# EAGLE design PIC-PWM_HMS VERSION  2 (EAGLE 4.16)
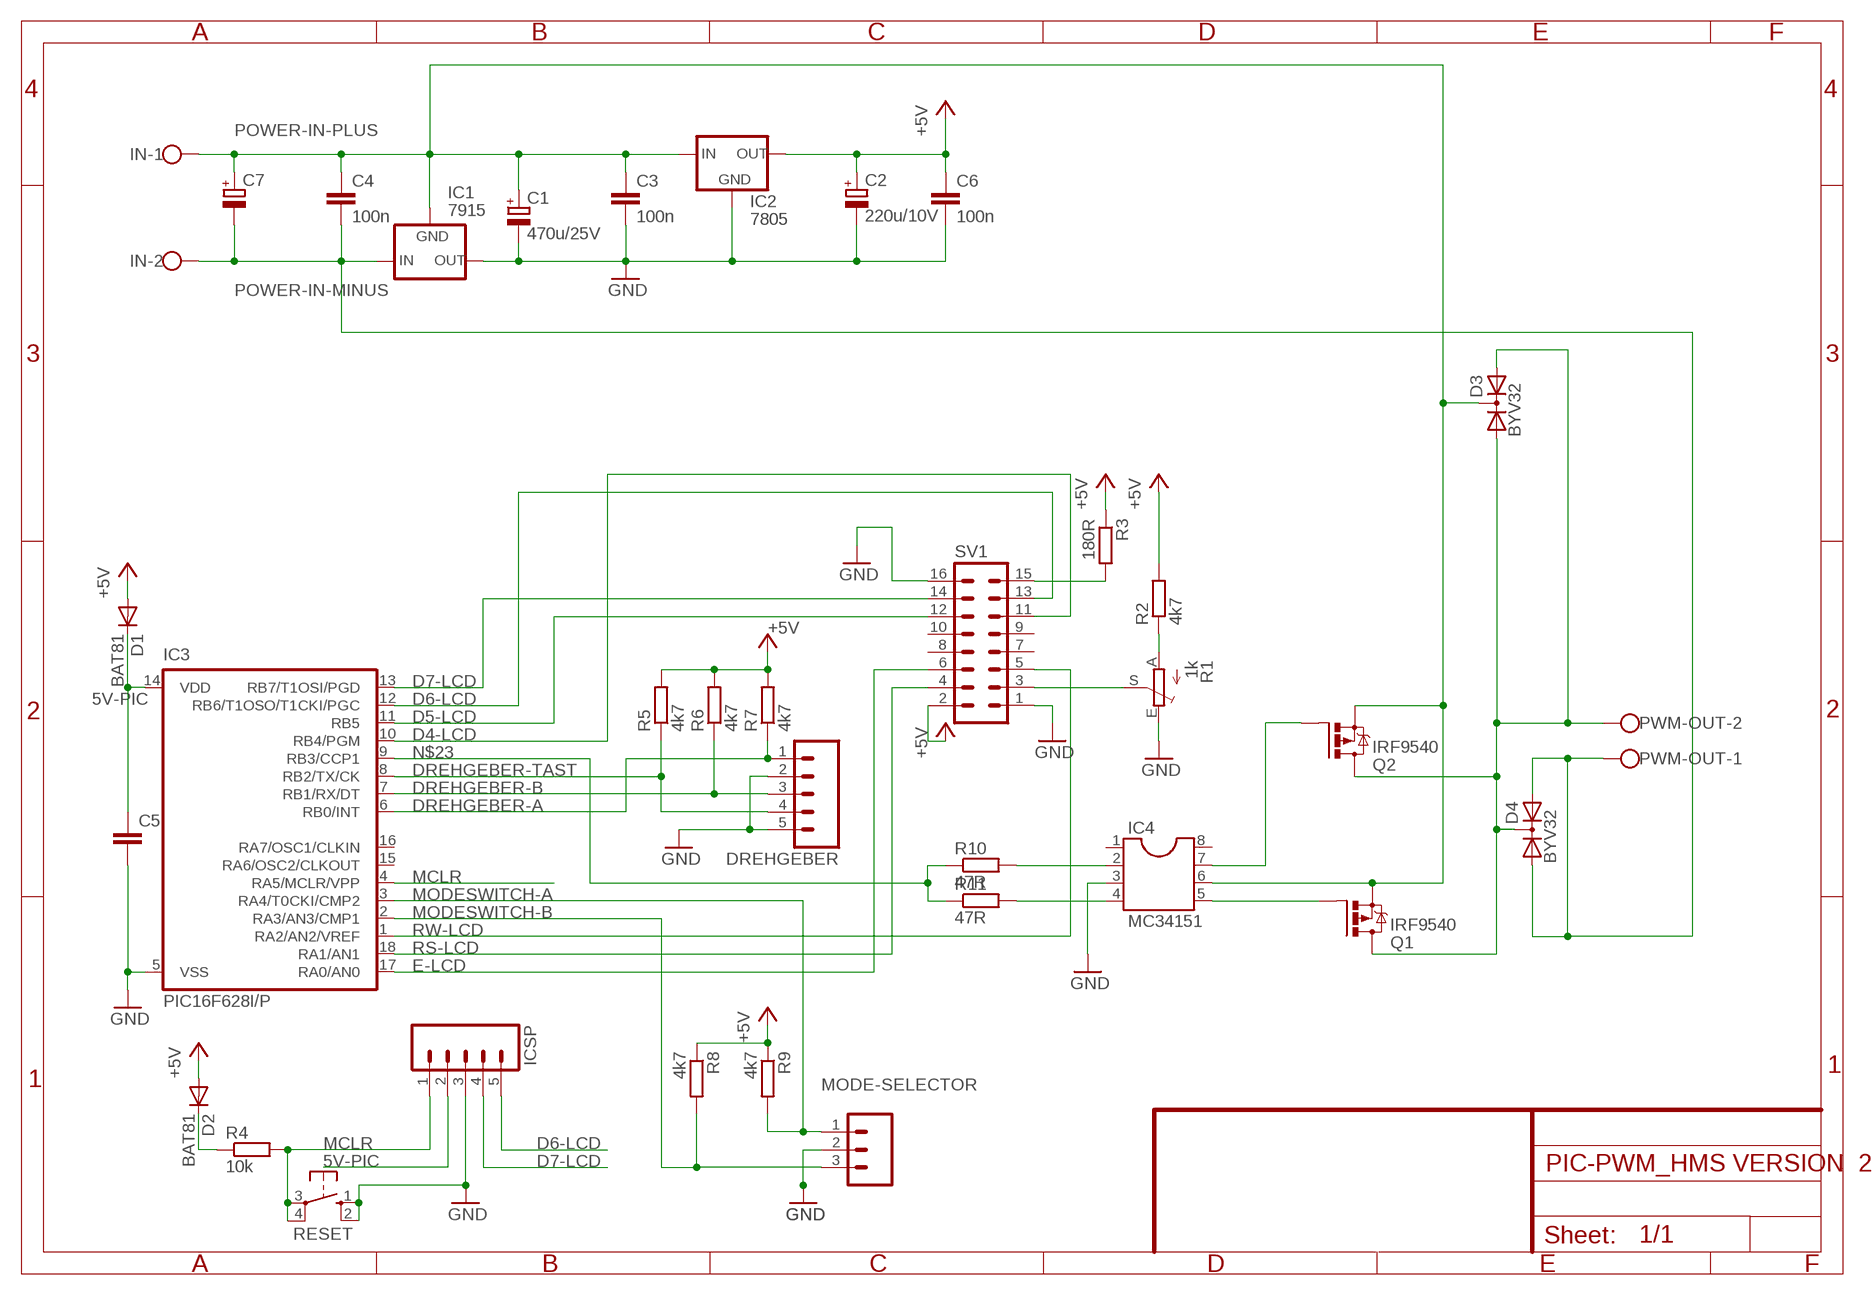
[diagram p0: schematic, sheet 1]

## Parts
C1  470u/25V  CPOL-EUE5-13  [E5-13]
C2  220u/10V  CPOL-EUE5-8.5  [E5-8,5]
C3  100n  C-EU050-024X044  [C050-024X044]
C4  100n  C-EU050-024X044  [C050-024X044]
C5  C-EU050-024X044  [C050-024X044]
C6  100n  C-EU050-024X044  [C050-024X044]
C7  CPOL-EUE10-25  [EB25D]
D1  BAT81  [DO34-7]
D2  BAT81  [DO34-7]
D3  BYV32  [TO220ABS]
D4  BYV32  [TO220ABS]
DREHGEBER  M05  [05P]
IC1  7915  79XXS  [79XXS]
IC2  7805  78MXXS  [78MXXS]
IC3  PIC16F628I/P  [DIL18]
IC4  MC34151  DIL8  [DIL08]
ICSP  M05  [05P]
IN  W237-02P  [W237-132]
MODE-SELECTOR  M03  [03P]
PWM-OUT  W237-02P  [W237-132]
Q1  IRF9540  [TO220BV]
Q2  IRF9540  [TO220BV]
R1  1k  TRIM_EU-CA9V  [CA9V]
R2  4k7  R-EU_0207/12  [0207/12]
R3  180R  R-EU_0309/12  [0309/12]
R4  10k  R-EU_0207/12  [0207/12]
R5  4k7  R-EU_0207/12  [0207/12]
R6  4k7  R-EU_0207/12  [0207/12]
R7  4k7  R-EU_0207/12  [0207/12]
R8  4k7  R-EU_0207/12  [0207/12]
R9  4k7  R-EU_0207/12  [0207/12]
R10  47R  R-EU_0207/12  [0207/12]
R11  47R  R-EU_0207/12  [0207/12]
RESET  10-XX  [B3F-10XX]
SV1  ML16  [ML16]

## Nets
5V-PIC: C5.1 D1.C IC3.14(VDD) ICSP.2
+5V: C2.+ C6.1 D1.A D2.A IC2.OUT R2.2 R3.1 R5.2 R6.2 R7.2 R8.1 R9.1 SV1.2
D4-LCD: IC3.10(RB4/PGM) SV1.11
D5-LCD: IC3.11(RB5) SV1.12
D6-LCD: IC3.12(RB6/T1OSO/T1CKI/PGC) ICSP.5 SV1.13
D7-LCD: IC3.13(RB7/T1OSI/PGD) ICSP.4 SV1.14
DREHGEBER-A: DREHGEBER.1 IC3.6(RB0/INT) R7.1
DREHGEBER-B: DREHGEBER.3 IC3.7(RB1/RX/DT) R6.1
DREHGEBER-TAST: DREHGEBER.4 IC3.8(RB2/TX/CK) R5.1
E-LCD: IC3.17(RA0/AN0) SV1.6
GND: C1.- C2.- C3.2 C5.2 C6.2 DREHGEBER.2 DREHGEBER.5 IC1.OUT IC2.GND IC3.5(VSS) IC4.3 ICSP.3 MODE-SELECTOR.2 R1.E RESET.1(S) RESET.2(S1) SV1.1 SV1.16
MCLR: IC3.4(RA5/MCLR/VPP) ICSP.1 R4.2 RESET.3(P) RESET.4(P1)
MODESWITCH-A: IC3.3(RA4/T0CKI/CMP2) MODE-SELECTOR.1 R9.2
MODESWITCH-B: IC3.2(RA3/AN3/CMP1) MODE-SELECTOR.3 R8.2
N$1: IC4.2 R10.2
N$2: IC4.4 R11.2
N$3: D2.C R4.1
N$4: R1.A R2.1
N$5: R1.S SV1.3
N$6: D3.A1 D3.A2 D4.C PWM-OUT.2 Q1.D Q2.D
N$8: IC4.5 Q1.G
N$9: IC4.7 Q2.G
N$11: R3.2 SV1.15
N$23: IC3.9(RB3/CCP1) R10.1 R11.1
POWER-IN-MINUS: C4.2 C7.- D4.A1 D4.A2 IC1.IN IN.2 PWM-OUT.1
POWER-IN-PLUS: C1.+ C3.1 C4.1 C7.+ D3.C IC1.GND IC2.IN IC4.6 IN.1 Q1.S Q2.S
RS-LCD: IC3.18(RA1/AN1) SV1.4
RW-LCD: IC3.1(RA2/AN2/VREF) SV1.5
Unconnected: IC3.15(RA6/OSC2/CLKOUT) IC3.16(RA7/OSC1/CLKIN) IC4.1 IC4.8 SV1.7 SV1.8 SV1.9 SV1.10

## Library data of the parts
C1 C2 C7 = rcl:CPOL-EU: POLARIZED CAPACITOR, European symbol
C3-C6 = rcl:C-EU: CAPACITOR, European symbol
D1 D2 = diode:BAT81: DIODE
D3 D4 = diode:BYV32: DIODE 2 x Si diode 200 V, 20 A/230 Apeak, 25 ns
DREHGEBER ICSP = con-amp-quick:M05: AMP QUICK CONNECTOR
IC1 = v-reg:79XXS: VOLTAGE REGULATOR
IC2 = v-reg:78MXXS: VOLTAGE REGULATOR
IC3 = microchip-5:PIC16F628*: MICROCONTROLLER PIC16F628(A) 16 I/O One 16-bit timer Two 8-bit timer Two comparators USART CCP/PWM Precision 4 MHz internal oscillator 2k Program Flash memory 224 bytes SRAM 128 bytes EEPROM
IC4 = ic-package:DIL8: Dual In Line
IN PWM-OUT = con-wago-508:W237-02P: WAGO SREW CLAMP
MODE-SELECTOR = con-amp-quick:M03: AMP QUICK CONNECTOR
Q1 Q2 = transistor-power:IRF9540: P-CHANNEL HEXFET POWER-MOS-FET Source: http://www.irf.com/product-info/datasheets/data/irf9530.pdf
R1 = pot:TRIM_EU-: POTENTIOMETER
R2-R11 = rcl:R-EU_: RESISTOR, European symbol
RESET = switch-omron:10-XX: OMRON SWITCH
SV1 = con-harting-ml:ML16: HARTING

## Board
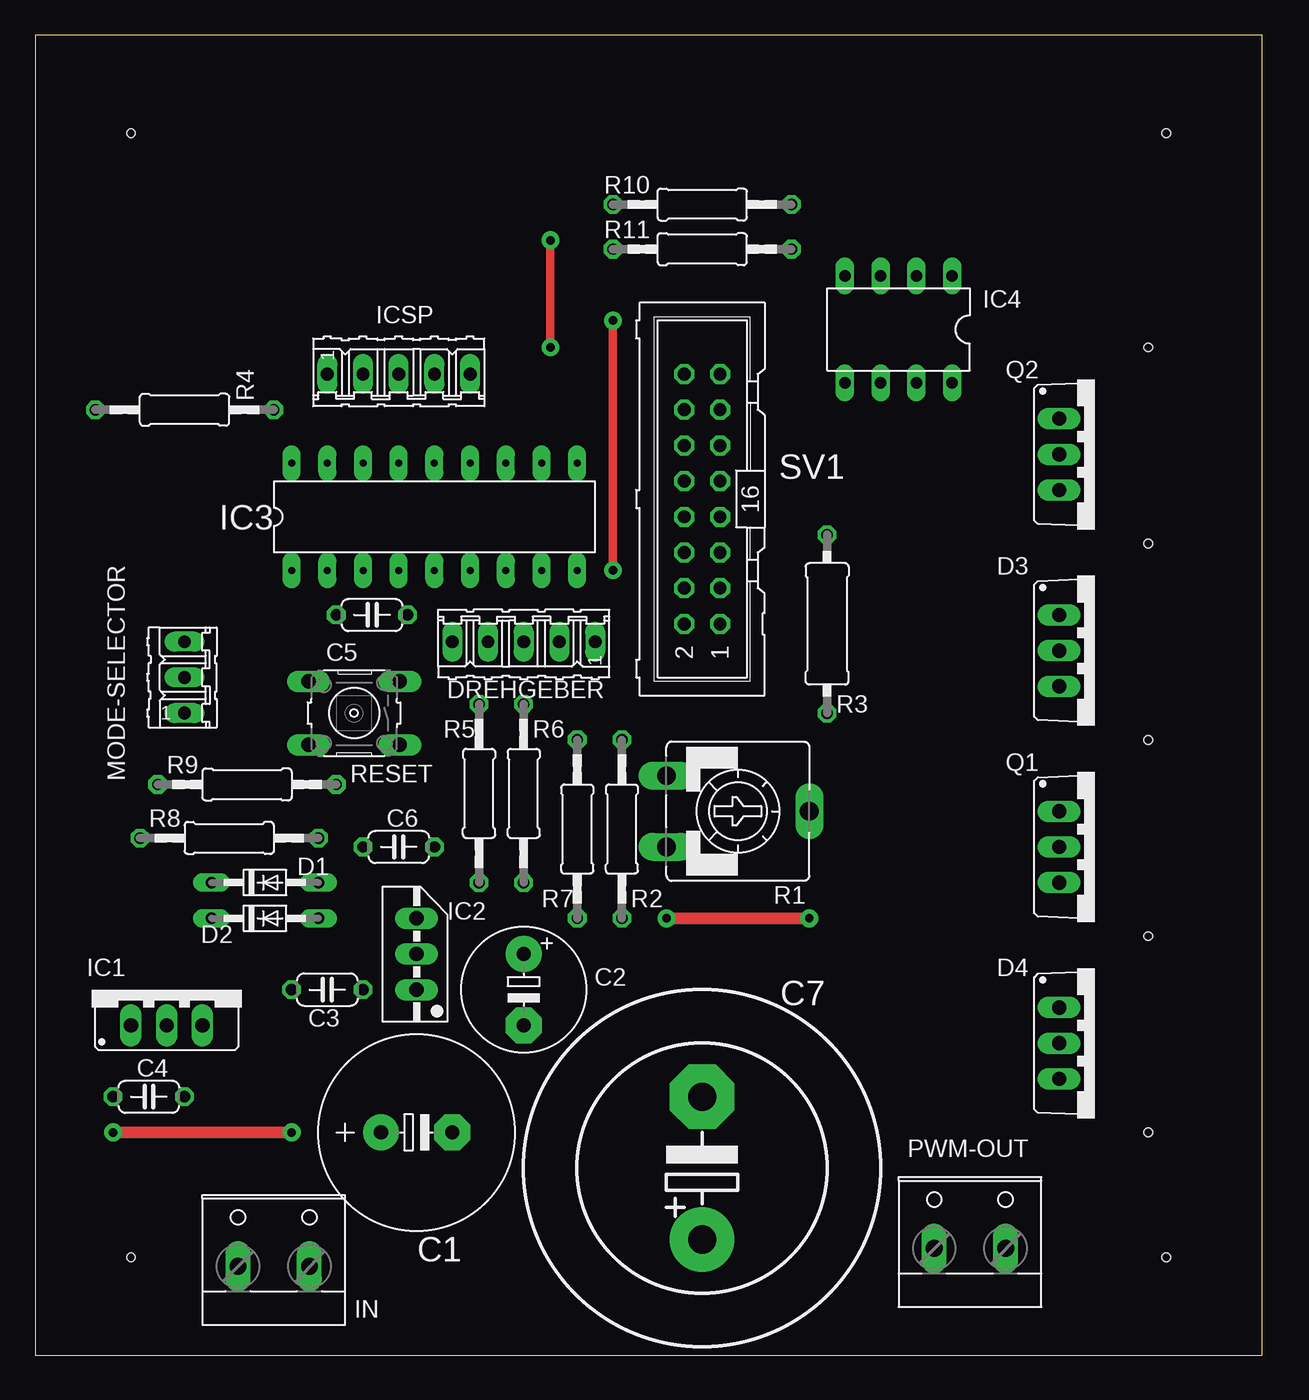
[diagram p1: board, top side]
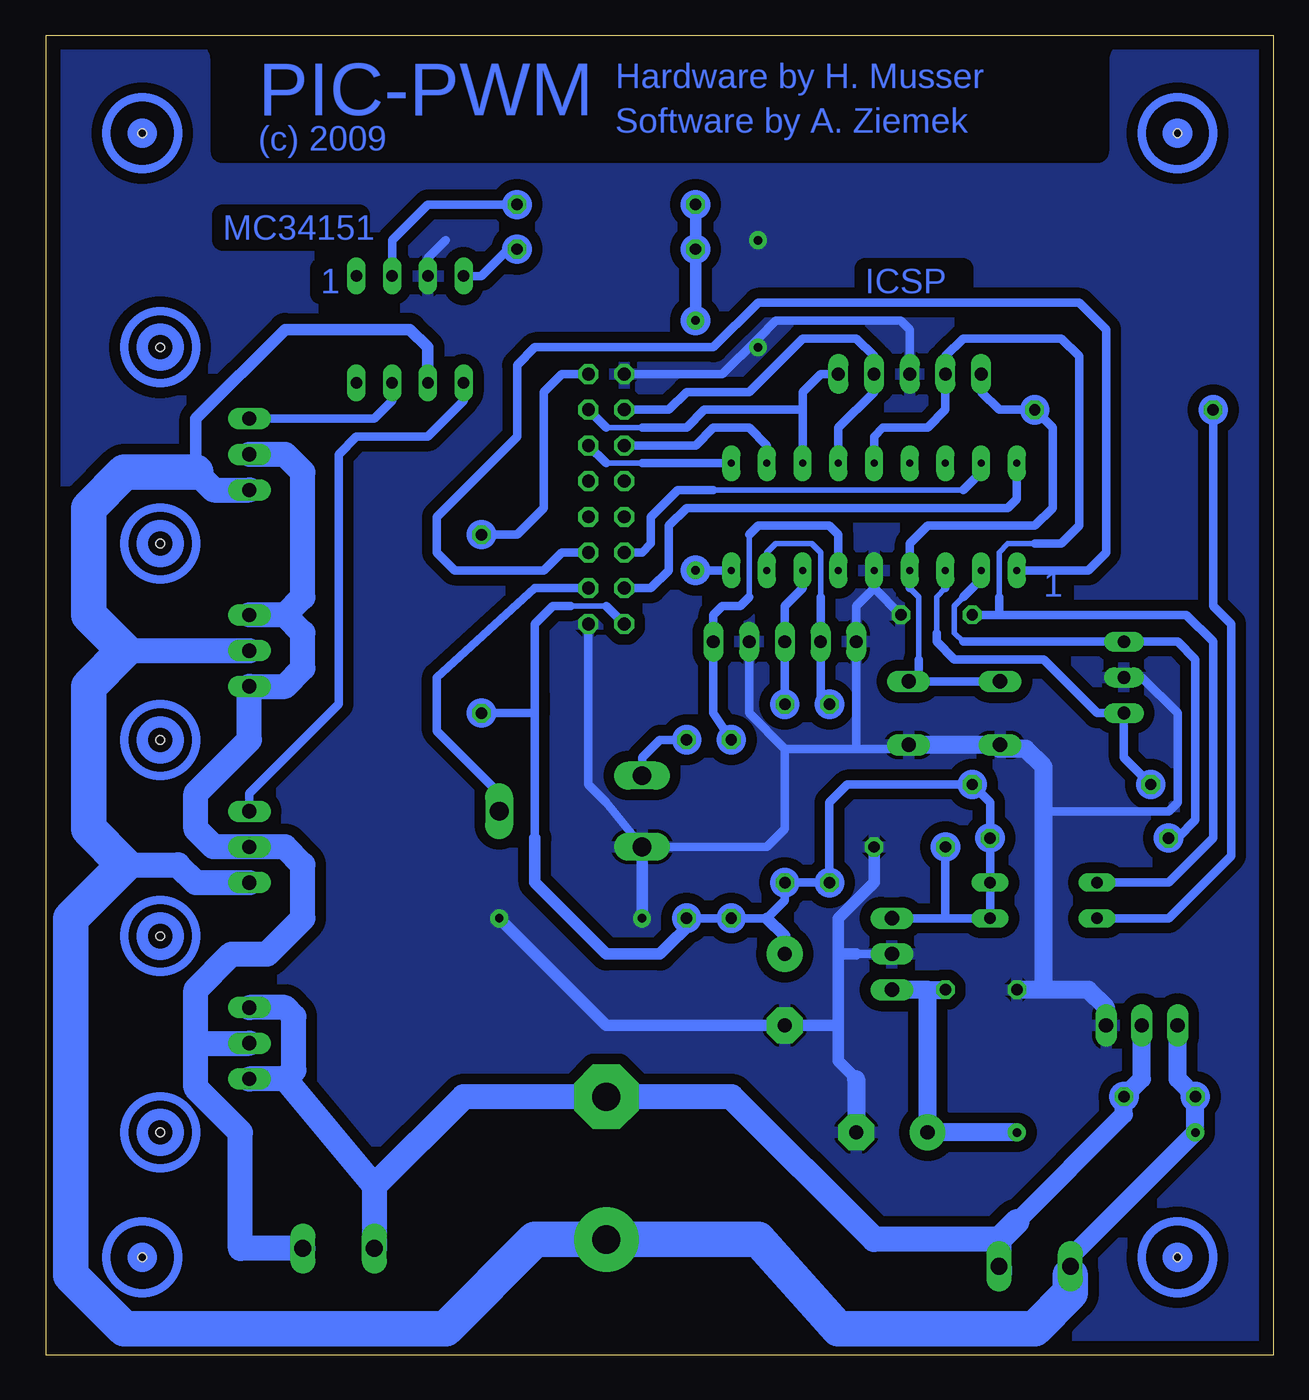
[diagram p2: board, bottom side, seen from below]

Size 87.3 x 93.96 mm. Coordinates in mm from the lower left corner, seen from the top.
Outline: 0,93.96 0,0 87.3,0 87.3,93.96 0,93.96
Copper layers (1*16): Top 0.035mm / dielectric 1.5mm / Bottom 0.035mm
Design rules "default": minimum track width 10mil, minimum drill 24mil, track to track 30mil, track to pad 30mil, pad to pad 30mil, via to via 30mil, smd to smd 30mil, copper to edge 40mil, drill to drill 8mil, minimum pad ring 10mil, minimum via ring 8mil, stop-mask expansion 4mil, vias tented up to drill 0mil, thermal gap 10mil
Holes 0.6 mm at 6.82,86.98 80.48,86.98 79.21,71.74 79.21,57.77 79.21,43.8 79.21,29.83 80.48,6.97 6.82,6.97 79.21,15.86

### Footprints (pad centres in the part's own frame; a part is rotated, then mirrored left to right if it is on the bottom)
E5-13 = drill 1.016 pad 2.54 round: + -2.54,0 | drill 1.016 pad 2.54 octagon: - 2.54,0
E5-8,5 = drill 1.016 pad 2.54 round: + -2.54,0 | drill 1.016 pad 2.54 octagon: - 2.54,0
C050-024X044 = drill 0.813 octagon: 1 -2.54,0; 2 2.54,0
EB25D = drill 2.007 pad 4.597 round: + -5.08,0 | drill 2.007 pad 4.597 octagon: - 5.08,0
DO34-7 = drill 0.813 long: A 3.81,0; C -3.81,0
TO220ABS = drill 1.016 long: A1 -2.54,-2.54; A2 2.54,-2.54; C 0,-2.54
05P = drill 0.914 long: 1 -5.08,0; 2 -2.54,0; 3 0,0; 4 2.54,0; 5 5.08,0
79XXS = drill 1.016 long: GND -2.54,-2.54; IN 0,-2.54; OUT 2.54,-2.54
78MXXS = drill 1.016 long: GND 0,-2.54; IN -2.54,-2.54; OUT 2.54,-2.54
DIL18 = drill 0.5 pad 1.27 long: 1 -10.16,-3.81; 2 -7.62,-3.81; 3 -5.08,-3.81; 4 -2.54,-3.81; 5 0,-3.81; 6 2.54,-3.81; 7 5.08,-3.81; 8 7.62,-3.81; 9 10.16,-3.81; 10 10.16,3.81; 11 7.62,3.81; 12 5.08,3.81; 13 2.54,3.81; 14 0,3.81; 15 -2.54,3.81; 16 -5.08,3.81; 17 -7.62,3.81; 18 -10.16,3.81
DIL08 = drill 0.813 long: 1 -3.81,-3.81; 2 -1.27,-3.81; 3 1.27,-3.81; 4 3.81,-3.81; 5 3.81,3.81; 6 1.27,3.81; 7 -1.27,3.81; 8 -3.81,3.81
W237-132 = drill 1.194 long: 1 -2.54,-0.635; 2 2.54,-0.635
03P = drill 0.914 long: 1 -2.54,0; 2 0,0; 3 2.54,0
TO220BV = drill 1.016 long: D 0,-2.54; G -2.54,-2.54; S 2.54,-2.54
CA9V = drill 1.321 long: A -2.54,-5.08; E 2.54,-5.08; S 0,5.08
0207/12 = drill 0.813 octagon: 1 -6.35,0; 2 6.35,0
0309/12 = drill 0.813 octagon: 1 -6.35,0; 2 6.35,0
B3F-10XX = drill 1.016 long: 1 -3.251,2.261; 2 3.251,2.261; 3 -3.251,-2.261; 4 3.251,-2.261
ML16 = drill 0.914 octagon: 1 -8.89,-1.27; 2 -8.89,1.27; 3 -6.35,-1.27; 4 -6.35,1.27; 5 -3.81,-1.27; 6 -3.81,1.27; 7 -1.27,-1.27; 8 -1.27,1.27; 9 1.27,-1.27; 10 1.27,1.27; 11 3.81,-1.27; 12 3.81,1.27; 13 6.35,-1.27; 14 6.35,1.27; 15 8.89,-1.27; 16 8.89,1.27

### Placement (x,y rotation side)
C1  27.14,15.86 0 top
C2  34.76,26.02 270 top
C3  20.79,26.02 180 top
C4  8.09,18.4 0 top
C5  23.96,52.69 0 top
C6  25.87,36.18 0 top
C7  47.46,13.32 90 top
D1  16.34,33.64 0 top
D2  16.34,31.1 0 top
D3  75.4,50.15 270 top
D4  75.4,22.21 270 top
DREHGEBER  34.76,50.79 180 top
IC1  9.36,26.02 0 top
IC2  24.6,28.56 90 top
IC3  28.41,59.68 0 top
IC4  61.43,73.01 180 top
ICSP  25.87,69.83 0 top
IN  16.98,6.97 0 top
MODE-SELECTOR  10.63,48.25 90 top
PWM-OUT  66.51,8.24 0 top
Q1  75.4,36.18 270 top
Q2  75.4,64.12 270 top
R1  50,38.72 270 top
R2  41.75,37.45 270 top
R3  56.35,52.05 90 top
R4  10.63,67.29 0 top
R5  31.58,39.99 270 top
R6  34.76,39.99 270 top
R7  38.57,37.45 270 top
R8  13.8,36.82 180 top
R9  15.07,40.62 180 top
R10  47.46,81.9 0 top
R11  47.46,78.72 0 top
RESET  22.7,45.7 180 top
SV1  47.46,60.95 90 top

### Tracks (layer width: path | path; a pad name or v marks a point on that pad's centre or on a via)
5V-PIC
  Bottom 0.406: 19.52,53.96 19.52,57.13 18.88,57.77 16.98,57.77
  Bottom 0.61: D1.C 7.46,33.64 4.28,36.82 4.28,50.79 6.19,52.69 19.52,52.69 | IC3.14 28.41,65.39 27.77,66.02 24.6,66.02 23.33,67.29 ICSP.2 23.33,71.1 22.06,72.38 15.07,72.38 13.8,71.1 13.8,59.04 15.07,57.77 16.98,57.77 | 19.52,52.69 C5.1 | 19.52,52.69 19.52,53.96
+5V
  Bottom 0.406: 50,53.33 47.46,53.33
  Bottom 0.61: 47.46,53.33 SV1.2 | 50,53.33 51.27,53.33 52.54,52.05 52.54,46.98 | 52.54,36.82 52.54,46.98 | R2.2 41.11,31.1 R7.2 36.03,31.1 34.76,32.37 R6.2 R5.2 31.58,39.36 30.31,40.62 R9.1 20.15,39.36 R8.1 D1.A D2.A 23.33,31.1 | 52.54,46.98 52.54,45.7 R3.1 | 23.33,31.1 IC2.OUT | 23.33,31.1 C6.1
  Bottom 0.813: C2.+ 34.76,29.83 36.03,31.1 | 52.54,36.82 52.54,33.64 47.46,28.56 43.65,28.56 41.11,31.1
D4-LCD
  Bottom 0.406: 44.92,63.49 47.46,63.49
  Bottom 0.61: 47.46,63.49 SV1.11 | IC3.10 44.92,63.49
D5-LCD
  Bottom 0.61: IC3.11 36.03,64.75 37.3,66.02 39.84,66.02 41.11,64.75 SV1.12
D6-LCD
  Bottom 0.406: 44.92,66.02 47.46,66.02
  Bottom 0.61: 47.46,66.02 SV1.13 | 44.92,66.02 41.75,66.02 40.48,67.29 33.49,67.29 | IC3.12 33.49,67.29 | 33.49,67.29 33.49,68.56 32.22,69.83 ICSP.5
D7-LCD
  Bottom 0.61: SV1.14 43.02,67.29 41.75,68.56 37.3,68.56 33.49,72.38 29.68,72.38 28.41,71.1 ICSP.4 28.41,68.56 30.95,66.02 IC3.13
DREHGEBER-A
  Bottom 0.406: 37.3,53.96 37.3,58.41
  Bottom 0.61: R7.1 39.84,45.7 DREHGEBER.1 39.84,52.69 39.21,53.33 37.94,53.33 37.3,53.96 | IC3.6 30.95,58.41 31.58,59.04 36.67,59.04 37.3,58.41
DREHGEBER-B
  Bottom 0.61: R6.1 DREHGEBER.3 34.76,53.33 33.49,54.59 IC3.7
DREHGEBER-TAST
  Bottom 0.406: 32.22,53.96 32.22,57.13 32.86,57.77 35.4,57.77 36.03,57.13 IC3.8
  Bottom 0.61: R5.1 32.22,46.98 DREHGEBER.4 32.22,53.96
E-LCD
  Bottom 0.406: 22.06,61.58 39.84,61.58
  Bottom 0.61: IC3.17 20.79,62.85 22.06,61.58 | 39.84,61.58 42.38,61.58 44.29,59.68 44.29,57.77 44.92,57.13 SV1.6
GND  (via drill 0.6 pad 1.27)
  Top 0.61: v36.67,71.74 v36.67,79.36
  Top 0.813: v44.92,31.1 v55.08,31.1
  Bottom 0.61: 28.41,54.59 IC3.5 | 28.41,54.59 29.68,53.33 DREHGEBER.5 29.68,43.16 | DREHGEBER.2 37.3,45.7 34.76,43.16 | 29.68,43.16 34.76,43.16 | SV1.1 48.73,40.62 47.46,39.36 R1.E 36.03,36.18 34.76,37.45 34.76,43.16 | 29.68,43.16 26.5,43.16 26.5,43.8 25.87,43.37 RESET.1 | MODE-SELECTOR.2 9.36,48.25 6.82,45.7 6.82,39.36 7.46,38.72 16.34,38.72 | 36.67,72.38 35.4,73.64 26.5,73.64 25.87,73.01 ICSP.3 | 36.67,72.38 39.21,69.83 SV1.16 | 28.41,54.59 C5.2 | 36.67,72.38 v36.67,71.74 | 58.89,79.36 60.16,78.09 IC4.3 | 30.95,28.56 30.95,31.1 | 29.68,28.56 IC2.GND
  Bottom 0.813: 29.68,28.56 30.95,28.56 30.95,23.48 | 30.95,23.48 C2.- | 29.68,19.67 30.95,20.94 30.95,23.48 | C6.2 28.41,33.64 30.95,31.1 30.95,23.48 | 30.95,23.48 47.46,23.48 v55.08,31.1 | R1.E v44.92,31.1
  Bottom 1.27: RESET.1 RESET.2 19.8,43.44 19.52,43.16 17.61,43.16 16.34,41.9 16.34,38.72 16.34,26.02 | 16.34,26.02 C3.2 | IC1.OUT 11.9,24.75 13.17,26.02 16.34,26.02 | 29.68,19.67 C1.-
  pour Bottom: 1.1,0.62 1.1,93.33 9.99,93.33 arc-90 11.26,92.06 11.26,85.71 arc90 12.54,84.44 74.77,84.44 arc90 76.03,85.71 76.03,92.06 arc-90 77.31,93.33 86.2,93.33 86.2,0.62
MCLR
  Bottom 0.406: 25.87,54.59 25.23,53.96 25.23,49.52
  Bottom 0.61: 26.5,48.25 25.87,48.25 | 26.5,48.25 26.58,48.17 RESET.3 | RESET.4 25.23,47.97 | 25.23,47.97 26.23,47.97 26.5,48.25 | ICSP.1 20.79,68.56 19.52,67.29 R4.2 15.71,66.02 15.71,60.31 16.98,59.04 24.6,59.04 25.87,57.77 IC3.4 25.87,54.59 | 25.23,47.97 25.23,49.52
MODESWITCH-A
  Bottom 0.406: 23.33,54.59 23.96,53.96 23.96,51.42
  Bottom 0.61: R9.2 10.63,42.53 MODE-SELECTOR.1 12.54,45.7 16.34,49.52 22.7,49.52 23.96,50.79 23.96,51.42 | 23.33,54.59 IC3.3
MODESWITCH-B
  Bottom 0.406: 22.06,53.96 22.7,53.33 22.7,51.42 22.06,50.79
  Bottom 0.61: R8.2 6.82,36.82 5.55,38.09 5.55,49.52 6.82,50.79 MODE-SELECTOR.3 22.06,50.79 | IC3.2 20.79,55.23 22.06,53.96
N$1
  Bottom 0.61: R10.2 60.16,81.9 62.7,79.36 IC4.2
N$2
  Bottom 0.61: R11.2 54.45,78.72 56.35,76.82 IC4.4
N$3
  Bottom 0.61: R4.1 4.28,53.33 3.01,52.05 3.01,35.55 7.46,31.1 D2.C
N$4
  Bottom 0.61: R2.1 43.65,43.8 44.92,42.53 R1.A
N$5
  Bottom 0.61: SV1.3 52.54,54.59 59.53,48.25 59.53,44.44 55.08,39.99 R1.S
N$6
  Bottom 1.778: PWM-OUT.2 73.5,7.61 73.5,15.86 76.67,19.04 76.67,22.21 | 76.67,22.21 D4.C | 76.67,22.21 76.67,26.02 74.13,28.56 71.59,28.56 69.05,31.1 69.05,34.91 70.32,36.18 Q1.D 75.4,36.18 76.67,37.45 76.67,39.99 72.86,43.8 D3.A2 70.32,47.61 69.05,48.88 69.05,51.42 70.32,52.69 | 70.32,52.69 D3.A1 | 70.32,52.69 69.05,53.96 69.05,62.85 70.32,64.12 Q2.D
N$8
  Bottom 0.61: IC4.5 57.62,67.93 60.16,65.39 65.24,65.39 66.51,64.12 66.51,46.34 72.86,39.99 Q1.G
N$9
  Bottom 0.61: IC4.7 62.7,67.93 63.97,66.66 Q2.G
N$11
  Bottom 0.61: R3.2 53.81,58.41 51.91,60.31 51.91,68.56 50.64,69.83 SV1.15
N$23  (via drill 0.6 pad 1.27)
  Top 0.61: v41.11,55.87 v41.11,73.64
  Bottom 0.61: IC3.9 v41.11,55.87 | v41.11,73.64 41.11,74.28 R11.1
  Bottom 0.813: R10.1 41.11,74.28 41.11,73.01
POWER-IN-MINUS
  Bottom 1.27: IC1.IN 9.36,19.67 C4.2 10.63,17.13 18.25,9.51
  Bottom 1.778: 63.97,12.05 PWM-OUT.1 | 63.97,12.05 70.32,19.67 | 19.52,5.7 IN.2 19.52,8.24 | 70.32,19.67 D4.A2 | 70.32,19.67 69.69,20.3 69.69,24.12 70.32,24.75 D4.A1 | 19.52,8.24 18.25,9.51 | 19.52,8.24 28.41,8.24 38.57,18.4 C7.- 57.62,18.4 63.97,12.05
POWER-IN-PLUS  (via drill 0.6 pad 1.27)
  Top 0.813: v5.55,15.86 v18.25,15.86
  Bottom 0.813: IC4.6 60.16,71.74 61.43,73.01 70.32,73.01 76.67,66.66 76.67,62.85
  Bottom 1.27: 24.6,26.02 IC2.IN | IC1.GND 6.82,19.67 C4.1 v5.55,15.86 14.44,6.97 IN.1 14.44,5.7 | 24.6,26.02 C3.1 | 24.6,26.02 C1.+ v18.25,15.86
  Bottom 1.778: 81.75,50.15 D3.C | 81.75,34.91 77.94,34.91 76.67,33.64 Q1.S | 76.67,62.85 75.4,61.58 Q2.S
  Bottom 2.54: 76.67,62.85 81.75,62.85 84.29,60.31 84.29,52.69 81.75,50.15 84.29,47.61 84.29,37.45 81.75,34.91 85.56,31.1 85.56,5.7 81.75,1.89 58.89,1.89 52.54,8.24 C7.+ 36.67,8.24 30.95,1.89 16.98,1.89 14.44,4.43 14.44,5.7
RS-LCD
  Bottom 0.61: IC3.18 18.25,60.95 18.88,60.31 41.75,60.31 43.02,59.04 43.02,55.87 44.29,54.59 SV1.4
RW-LCD
  Bottom 0.61: SV1.5 50.64,57.13 51.91,55.87 58.26,55.87 59.53,57.13 59.53,59.68 53.81,65.39 53.81,70.47 52.54,71.74 39.84,71.74 36.67,74.91 13.8,74.91 11.9,73.01 11.9,57.13 13.17,55.87 IC3.1
(copper drawn outside any net)
  shapes: Bottom circle x43

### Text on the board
Bottom: Hardware by H. Musser | PIC-PWM | Software by A. Ziemek | (c) 2009 | MC34151 | ICSP | 1 | 1
Text: Hardware by H. Musser | PIC-PWM | Software by A. Ziemek | (c) 2009 | 1 | 1 | 1 | 1 | KONTRAST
